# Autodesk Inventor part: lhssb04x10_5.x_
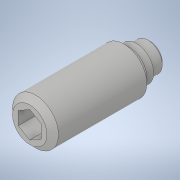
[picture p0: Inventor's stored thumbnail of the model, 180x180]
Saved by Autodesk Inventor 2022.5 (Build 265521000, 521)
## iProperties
Created: 2021-02
Part Number: lhssb04x10_5.x_
Material: 一般
Document SubType Name: Modeling
Designer: ImaoCorp
Density: 1 g/cm^3
Appearance: 既定
Sending System: SOLIDWORKS 2019-2019304
MC: AMD64
MC_MODEL: Intel64 Family 6 Model 60 Stepping 3, GenuineIntel
OS: Windows_NT
FRU: Parasolid Version 31.0, build 290,  9- 1-2019
FORMAT: text
GUISE: transmit
KEY: lhssb04x10_5
FILE: lhssb04x10_5.x_t
DATE: Mon Feb 22 14:56:28 2021
Author: ImaoCorp
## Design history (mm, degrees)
feature "Base1"
node "ソリッド1"
